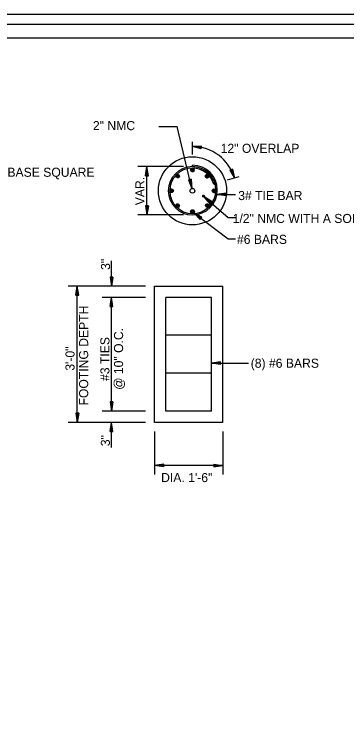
# Model space of a CAD drawing. Extents: x 1695551 to 1695718, y 544410 to 544516.
# Drawn here: x 1695642.8 to 1695670.2, y 544457.3 to 544516.2 of the extents above; entities that cross this region are included whole.
import ezdxf

# ---------------------------------------------------------------- set-up
doc = ezdxf.new("R2010")
doc.units = 0
for name, color, linetype in [('0_Plot Shape', 7, 'Continuous'), ('R_Border', 7, 'Continuous'), ('R_Draft', 7, 'Continuous'), ('R_No Plot', 7, 'Continuous')]:
    doc.layers.add(name, color=color, linetype=linetype)

msp = doc.modelspace()

# ---------------------------------------------------------------- linework, layer by layer
at = {"layer": '0_Plot Shape'}
msp.add_lwpolyline([(1695551.694, 544515.386), (1695716.694, 544515.386), (1695716.694, 544410.386), (1695551.694, 544410.386)], close=True, dxfattribs=at)
at = {"layer": 'R_Border'}
msp.add_line((1695557.469, 544514.251), (1695715.559, 544514.251), dxfattribs=at)
at = {"layer": 'R_Draft'}
for p, q in [((1695654.739, 544506.923), (1695656.274, 544506.923)), ((1695657.478, 544501.819), (1695656.274, 544506.923)), ((1695657.523, 544504.629), (1695657.523, 544505.656)), ((1695658.282, 544505.313), (1695657.524, 544505.297)), ((1695658.253, 544505.09), (1695657.524, 544505.297)), ((1695658.279, 544505.295), (1695657.648, 544505.281)), ((1695658.256, 544505.109), (1695657.648, 544505.281)), ((1695658.277, 544505.276), (1695657.776, 544505.264)), ((1695658.258, 544505.128), (1695657.776, 544505.264)), ((1695658.275, 544505.257), (1695657.9, 544505.249)), ((1695658.26, 544505.146), (1695657.9, 544505.249)), ((1695658.272, 544505.238), (1695658.026, 544505.233)), ((1695658.263, 544505.166), (1695658.026, 544505.233)), ((1695658.27, 544505.219), (1695658.15, 544505.217)), ((1695658.265, 544505.184), (1695658.15, 544505.217)), ((1695658.253, 544505.09), (1695658.282, 544505.313)), ((1695657.523, 544503.622), (1695657.523, 544503.739)), ((1695656.773, 544503.622), (1695653.023, 544503.622)), ((1695653.66, 544502.872), (1695653.773, 544503.622)), ((1695653.679, 544502.872), (1695653.773, 544503.497)), ((1695653.698, 544502.872), (1695653.773, 544503.368)), ((1695653.717, 544502.872), (1695653.773, 544503.243)), ((1695653.736, 544502.872), (1695653.773, 544503.116)), ((1695653.773, 544499.637), (1695653.773, 544503.622)), ((1695653.885, 544502.872), (1695653.773, 544503.622)), ((1695653.866, 544502.872), (1695653.773, 544503.497)), ((1695653.847, 544502.872), (1695653.773, 544503.368)), ((1695653.828, 544502.872), (1695653.773, 544503.243)), ((1695653.809, 544502.872), (1695653.773, 544503.116)), ((1695657.373, 544503.348), (1695657.529, 544503.504)), ((1695657.374, 544503.375), (1695657.501, 544503.503)), ((1695657.376, 544503.324), (1695657.553, 544503.501)), ((1695657.381, 544503.303), (1695657.574, 544503.495)), ((1695657.384, 544503.412), (1695657.465, 544503.493)), ((1695657.39, 544503.285), (1695657.592, 544503.487)), ((1695657.4, 544503.268), (1695657.608, 544503.477)), ((1695657.411, 544503.254), (1695657.623, 544503.465)), ((1695657.425, 544503.241), (1695657.636, 544503.452)), ((1695657.44, 544503.229), (1695657.648, 544503.437)), ((1695657.457, 544503.219), (1695657.657, 544503.42)), ((1695657.476, 544503.212), (1695657.665, 544503.401)), ((1695657.497, 544503.206), (1695657.67, 544503.38)), ((1695657.521, 544503.204), (1695657.673, 544503.356)), ((1695657.55, 544503.207), (1695657.67, 544503.327)), ((1695657.59, 544503.22), (1695657.656, 544503.286)), ((1695660.815, 544503.413), (1695660.605, 544503.332)), ((1695660.605, 544503.332), (1695660.978, 544502.672)), ((1695660.622, 544503.339), (1695660.933, 544502.789)), ((1695660.64, 544503.346), (1695660.887, 544502.909)), ((1695660.658, 544503.352), (1695660.842, 544503.026)), ((1695660.675, 544503.359), (1695660.797, 544503.145)), ((1695660.693, 544503.366), (1695660.752, 544503.262)), ((1695660.726, 544503.379), (1695660.752, 544503.262)), ((1695660.744, 544503.385), (1695660.797, 544503.145)), ((1695660.762, 544503.392), (1695660.842, 544503.026)), ((1695660.779, 544503.399), (1695660.887, 544502.909)), ((1695660.797, 544503.406), (1695660.933, 544502.789)), ((1695660.815, 544503.413), (1695660.978, 544502.672)), ((1695653.66, 544502.872), (1695653.885, 544502.872)), ((1695653.755, 544502.872), (1695653.773, 544502.99)), ((1695653.79, 544502.872), (1695653.773, 544502.99)), ((1695656.153, 544502.856), (1695656.296, 544502.999)), ((1695656.154, 544502.83), (1695656.322, 544502.998)), ((1695656.158, 544502.887), (1695656.265, 544502.994)), ((1695656.158, 544502.808), (1695656.344, 544502.993)), ((1695656.165, 544502.789), (1695656.363, 544502.986)), ((1695656.175, 544502.771), (1695656.381, 544502.977)), ((1695656.181, 544502.937), (1695656.215, 544502.971)), ((1695656.185, 544502.756), (1695656.396, 544502.966)), ((1695656.198, 544502.742), (1695656.41, 544502.954)), ((1695656.212, 544502.729), (1695656.422, 544502.939)), ((1695656.228, 544502.719), (1695656.433, 544502.923)), ((1695656.246, 544502.71), (1695656.442, 544502.906)), ((1695656.266, 544502.704), (1695656.448, 544502.886)), ((1695656.289, 544502.7), (1695656.452, 544502.863)), ((1695656.315, 544502.7), (1695656.452, 544502.837)), ((1695656.348, 544502.706), (1695656.446, 544502.804)), ((1695657.42, 544502.576), (1695657.201, 544502.525)), ((1695657.201, 544502.525), (1695657.478, 544501.819)), ((1695657.219, 544502.53), (1695657.45, 544501.941)), ((1695657.238, 544502.534), (1695657.421, 544502.067)), ((1695657.256, 544502.538), (1695657.393, 544502.189)), ((1695657.274, 544502.542), (1695657.365, 544502.313)), ((1695657.293, 544502.547), (1695657.337, 544502.435)), ((1695657.327, 544502.554), (1695657.337, 544502.435)), ((1695657.346, 544502.559), (1695657.365, 544502.313)), ((1695657.365, 544502.563), (1695657.393, 544502.189)), ((1695657.383, 544502.567), (1695657.421, 544502.067)), ((1695657.402, 544502.571), (1695657.45, 544501.941)), ((1695657.42, 544502.576), (1695657.478, 544501.819)), ((1695658.576, 544502.845), (1695658.713, 544502.982)), ((1695658.576, 544502.818), (1695658.739, 544502.981)), ((1695658.58, 544502.796), (1695658.762, 544502.978)), ((1695658.583, 544502.878), (1695658.679, 544502.975)), ((1695658.586, 544502.776), (1695658.782, 544502.971)), ((1695658.595, 544502.758), (1695658.8, 544502.962)), ((1695658.606, 544502.742), (1695658.816, 544502.952)), ((1695658.618, 544502.728), (1695658.83, 544502.94)), ((1695658.632, 544502.715), (1695658.842, 544502.926)), ((1695658.647, 544502.704), (1695658.853, 544502.91)), ((1695658.665, 544502.695), (1695658.863, 544502.893)), ((1695658.684, 544502.688), (1695658.87, 544502.873)), ((1695658.706, 544502.683), (1695658.874, 544502.851)), ((1695658.731, 544502.682), (1695658.875, 544502.826)), ((1695658.763, 544502.687), (1695658.871, 544502.795)), ((1695658.812, 544502.709), (1695658.848, 544502.746)), ((1695661.337, 544502.78), (1695660.395, 544502.496)), ((1695659.389, 544502.193), (1695659.277, 544502.159)), ((1695655.648, 544501.637), (1695655.79, 544501.779)), ((1695655.649, 544501.611), (1695655.816, 544501.778)), ((1695655.653, 544501.589), (1695655.838, 544501.774)), ((1695655.653, 544501.668), (1695655.759, 544501.774)), ((1695655.66, 544501.569), (1695655.857, 544501.767)), ((1695655.669, 544501.552), (1695655.875, 544501.758)), ((1695655.678, 544501.72), (1695655.707, 544501.749)), ((1695655.68, 544501.536), (1695655.891, 544501.747)), ((1695655.692, 544501.522), (1695655.905, 544501.734)), ((1695655.707, 544501.51), (1695655.917, 544501.72)), ((1695655.723, 544501.499), (1695655.927, 544501.704)), ((1695655.74, 544501.491), (1695655.936, 544501.686)), ((1695655.76, 544501.484), (1695655.943, 544501.667)), ((1695655.783, 544501.48), (1695655.947, 544501.644)), ((1695655.809, 544501.48), (1695655.947, 544501.618)), ((1695655.842, 544501.486), (1695655.941, 544501.585)), ((1695659.149, 544501.631), (1695659.297, 544501.779)), ((1695659.151, 544501.606), (1695659.322, 544501.778)), ((1695659.153, 544501.661), (1695659.267, 544501.776)), ((1695659.156, 544501.585), (1695659.344, 544501.773)), ((1695659.163, 544501.566), (1695659.363, 544501.765)), ((1695659.169, 544501.704), (1695659.224, 544501.759)), ((1695659.173, 544501.549), (1695659.38, 544501.756)), ((1695659.184, 544501.533), (1695659.395, 544501.745)), ((1695659.197, 544501.52), (1695659.409, 544501.732)), ((1695659.211, 544501.508), (1695659.421, 544501.717)), ((1695659.228, 544501.497), (1695659.431, 544501.701)), ((1695659.246, 544501.489), (1695659.439, 544501.683)), ((1695659.266, 544501.483), (1695659.445, 544501.662)), ((1695659.289, 544501.48), (1695659.449, 544501.639)), ((1695659.316, 544501.48), (1695659.448, 544501.612)), ((1695659.351, 544501.489), (1695659.44, 544501.577)), ((1695660.291, 544501.433), (1695659.541, 544501.321)), ((1695660.291, 544501.415), (1695659.666, 544501.321)), ((1695660.291, 544501.396), (1695659.795, 544501.321)), ((1695660.291, 544501.377), (1695659.92, 544501.321)), ((1695660.291, 544501.358), (1695660.047, 544501.321)), ((1695660.291, 544501.208), (1695660.291, 544501.433)), ((1695658.369, 544501.192), (1695658.446, 544501.27)), ((1695658.372, 544501.169), (1695658.469, 544501.267)), ((1695658.377, 544501.228), (1695658.411, 544501.261)), ((1695658.38, 544501.151), (1695658.488, 544501.258)), ((1695658.392, 544501.136), (1695658.502, 544501.247)), ((1695658.407, 544501.125), (1695658.514, 544501.232)), ((1695658.425, 544501.117), (1695658.522, 544501.213)), ((1695658.449, 544501.114), (1695658.525, 544501.19)), ((1695658.486, 544501.124), (1695658.514, 544501.153)), ((1695658.502, 544501.135), (1695660.474, 544499.414)), ((1695658.996, 544500.56), (1695658.502, 544501.135)), ((1695659.143, 544500.73), (1695658.502, 544501.135)), ((1695659.008, 544500.574), (1695658.597, 544501.053)), ((1695659.131, 544500.716), (1695658.597, 544501.053)), ((1695659.118, 544500.701), (1695658.694, 544500.969)), ((1695659.021, 544500.588), (1695658.694, 544500.969)), ((1695659.033, 544500.603), (1695658.789, 544500.887)), ((1695659.106, 544500.687), (1695658.789, 544500.887)), ((1695659.094, 544500.673), (1695658.885, 544500.804)), ((1695659.046, 544500.617), (1695658.885, 544500.804)), ((1695659.541, 544501.321), (1695661.075, 544501.321)), ((1695660.291, 544501.208), (1695659.541, 544501.321)), ((1695660.291, 544501.227), (1695659.666, 544501.321)), ((1695660.291, 544501.246), (1695659.795, 544501.321)), ((1695660.291, 544501.265), (1695659.92, 544501.321)), ((1695660.291, 544501.285), (1695660.047, 544501.321)), ((1695660.291, 544501.339), (1695660.172, 544501.321)), ((1695660.291, 544501.303), (1695660.172, 544501.321)), ((1695653.66, 544500.387), (1695653.773, 544499.637)), ((1695653.885, 544500.387), (1695653.66, 544500.387)), ((1695653.679, 544500.387), (1695653.773, 544499.762)), ((1695653.698, 544500.387), (1695653.773, 544499.891)), ((1695653.717, 544500.387), (1695653.773, 544500.016)), ((1695653.736, 544500.387), (1695653.773, 544500.143)), ((1695653.755, 544500.387), (1695653.773, 544500.268)), ((1695653.885, 544500.387), (1695653.773, 544499.637)), ((1695653.809, 544500.387), (1695653.773, 544500.143)), ((1695653.847, 544500.387), (1695653.773, 544499.891)), ((1695653.866, 544500.387), (1695653.773, 544499.762)), ((1695653.828, 544500.387), (1695653.773, 544500.016)), ((1695653.79, 544500.387), (1695653.773, 544500.268)), ((1695656.153, 544500.396), (1695656.317, 544500.559)), ((1695656.153, 544500.422), (1695656.29, 544500.559)), ((1695656.157, 544500.373), (1695656.339, 544500.555)), ((1695656.16, 544500.455), (1695656.257, 544500.552)), ((1695656.164, 544500.353), (1695656.359, 544500.548)), ((1695656.172, 544500.335), (1695656.377, 544500.54)), ((1695656.183, 544500.319), (1695656.393, 544500.529)), ((1695656.195, 544500.305), (1695656.407, 544500.517)), ((1695656.209, 544500.292), (1695656.42, 544500.503)), ((1695656.225, 544500.281), (1695656.431, 544500.488)), ((1695656.242, 544500.272), (1695656.44, 544500.47)), ((1695656.262, 544500.265), (1695656.447, 544500.451)), ((1695656.284, 544500.261), (1695656.452, 544500.429)), ((1695656.309, 544500.26), (1695656.453, 544500.403)), ((1695656.34, 544500.264), (1695656.448, 544500.372)), ((1695656.39, 544500.287), (1695656.425, 544500.322)), ((1695658.6, 544500.409), (1695658.742, 544500.552)), ((1695658.601, 544500.384), (1695658.768, 544500.551)), ((1695658.605, 544500.362), (1695658.79, 544500.547)), ((1695658.605, 544500.441), (1695658.711, 544500.547)), ((1695658.612, 544500.342), (1695658.81, 544500.54)), ((1695658.621, 544500.325), (1695658.827, 544500.531)), ((1695658.63, 544500.492), (1695658.659, 544500.522)), ((1695658.632, 544500.309), (1695658.843, 544500.52)), ((1695658.645, 544500.295), (1695658.857, 544500.507)), ((1695658.659, 544500.283), (1695658.869, 544500.493)), ((1695658.675, 544500.272), (1695658.88, 544500.477)), ((1695658.693, 544500.263), (1695658.888, 544500.459)), ((1695658.713, 544500.257), (1695658.895, 544500.439)), ((1695658.735, 544500.253), (1695658.899, 544500.417)), ((1695658.761, 544500.253), (1695658.899, 544500.39)), ((1695658.794, 544500.259), (1695658.893, 544500.358)), ((1695659.081, 544500.658), (1695658.98, 544500.722)), ((1695659.058, 544500.631), (1695658.98, 544500.722)), ((1695658.996, 544500.56), (1695659.143, 544500.73)), ((1695656.773, 544499.637), (1695653.023, 544499.637)), ((1695657.367, 544499.896), (1695657.537, 544500.066)), ((1695657.367, 544499.922), (1695657.511, 544500.066)), ((1695657.371, 544499.873), (1695657.56, 544500.062)), ((1695657.373, 544499.955), (1695657.478, 544500.06)), ((1695657.377, 544499.853), (1695657.58, 544500.056)), ((1695657.386, 544499.835), (1695657.598, 544500.047)), ((1695657.396, 544499.819), (1695657.614, 544500.037)), ((1695657.407, 544500.016), (1695657.417, 544500.026)), ((1695657.408, 544499.804), (1695657.629, 544500.025)), ((1695657.421, 544499.791), (1695657.642, 544500.012)), ((1695657.437, 544499.78), (1695657.653, 544499.997)), ((1695657.453, 544499.77), (1695657.663, 544499.98)), ((1695657.472, 544499.763), (1695657.67, 544499.961)), ((1695657.493, 544499.757), (1695657.676, 544499.94)), ((1695657.517, 544499.754), (1695657.679, 544499.916)), ((1695657.545, 544499.756), (1695657.677, 544499.888)), ((1695657.581, 544499.766), (1695657.667, 544499.852)), ((1695657.635, 544499.801), (1695660.474, 544497.654)), ((1695658.166, 544499.26), (1695657.635, 544499.801)), ((1695658.301, 544499.44), (1695657.635, 544499.801)), ((1695658.177, 544499.275), (1695657.735, 544499.726)), ((1695658.29, 544499.425), (1695657.735, 544499.726)), ((1695658.279, 544499.41), (1695657.838, 544499.648)), ((1695658.189, 544499.29), (1695657.838, 544499.648)), ((1695658.2, 544499.305), (1695657.937, 544499.573)), ((1695658.267, 544499.395), (1695657.937, 544499.573)), ((1695658.256, 544499.379), (1695658.039, 544499.497)), ((1695658.212, 544499.321), (1695658.039, 544499.497)), ((1695658.244, 544499.364), (1695658.139, 544499.421)), ((1695658.223, 544499.336), (1695658.139, 544499.421)), ((1695658.166, 544499.26), (1695658.301, 544499.44)), ((1695660.474, 544499.414), (1695661.075, 544499.414)), ((1695660.474, 544497.654), (1695661.075, 544497.654)), ((1695650.839, 544493.762), (1695650.839, 544495.847)), ((1695650.726, 544494.512), (1695650.839, 544493.762)), ((1695650.951, 544494.512), (1695650.726, 544494.512)), ((1695650.745, 544494.512), (1695650.839, 544493.888)), ((1695650.764, 544494.512), (1695650.839, 544494.017)), ((1695650.783, 544494.512), (1695650.839, 544494.142)), ((1695650.802, 544494.512), (1695650.839, 544494.269)), ((1695650.821, 544494.512), (1695650.839, 544494.394)), ((1695650.951, 544494.512), (1695650.839, 544493.762)), ((1695650.875, 544494.512), (1695650.839, 544494.269)), ((1695650.914, 544494.512), (1695650.839, 544494.017)), ((1695650.933, 544494.512), (1695650.839, 544493.888)), ((1695650.895, 544494.512), (1695650.839, 544494.142)), ((1695650.857, 544494.512), (1695650.839, 544494.394)), ((1695653.651, 544493.762), (1695647.276, 544493.762)), ((1695647.914, 544493.012), (1695648.026, 544493.762)), ((1695648.026, 544482.512), (1695648.026, 544493.762)), ((1695648.139, 544493.012), (1695648.026, 544493.762)), ((1695654.401, 544482.512), (1695654.401, 544493.762)), ((1695654.401, 544493.762), (1695660.026, 544493.762)), ((1695660.026, 544482.512), (1695660.026, 544493.762)), ((1695647.933, 544493.012), (1695648.026, 544493.637)), ((1695647.952, 544493.012), (1695648.026, 544493.508)), ((1695647.971, 544493.012), (1695648.026, 544493.383)), ((1695647.99, 544493.012), (1695648.026, 544493.256)), ((1695648.009, 544493.012), (1695648.026, 544493.131)), ((1695648.12, 544493.012), (1695648.026, 544493.637)), ((1695648.101, 544493.012), (1695648.026, 544493.508)), ((1695648.082, 544493.012), (1695648.026, 544493.383)), ((1695648.063, 544493.012), (1695648.026, 544493.256)), ((1695648.044, 544493.012), (1695648.026, 544493.131)), ((1695647.914, 544493.012), (1695648.139, 544493.012)), ((1695653.651, 544492.825), (1695650.089, 544492.825)), ((1695650.726, 544492.075), (1695650.839, 544492.825)), ((1695650.745, 544492.075), (1695650.839, 544492.7)), ((1695650.764, 544492.075), (1695650.839, 544492.571)), ((1695650.839, 544483.45), (1695650.839, 544492.825)), ((1695650.951, 544492.075), (1695650.839, 544492.825)), ((1695650.933, 544492.075), (1695650.839, 544492.7)), ((1695650.914, 544492.075), (1695650.839, 544492.571)), ((1695659.089, 544492.825), (1695655.339, 544492.825)), ((1695655.339, 544483.45), (1695655.339, 544492.825)), ((1695659.089, 544483.45), (1695659.089, 544492.825)), ((1695650.726, 544492.075), (1695650.951, 544492.075)), ((1695650.783, 544492.075), (1695650.839, 544492.446)), ((1695650.803, 544492.075), (1695650.839, 544492.319)), ((1695650.821, 544492.075), (1695650.839, 544492.193)), ((1695650.895, 544492.075), (1695650.839, 544492.446)), ((1695650.876, 544492.075), (1695650.839, 544492.319)), ((1695650.857, 544492.075), (1695650.839, 544492.193)), ((1695659.089, 544489.7), (1695655.339, 544489.7)), ((1695659.841, 544487.51), (1695659.091, 544487.397)), ((1695659.841, 544487.285), (1695659.091, 544487.397)), ((1695659.091, 544487.397), (1695662.145, 544487.397)), ((1695659.841, 544487.491), (1695659.216, 544487.397)), ((1695659.841, 544487.303), (1695659.216, 544487.397)), ((1695659.841, 544487.472), (1695659.345, 544487.397)), ((1695659.841, 544487.323), (1695659.345, 544487.397)), ((1695659.841, 544487.453), (1695659.47, 544487.397)), ((1695659.841, 544487.341), (1695659.47, 544487.397)), ((1695659.841, 544487.434), (1695659.597, 544487.397)), ((1695659.841, 544487.361), (1695659.597, 544487.397)), ((1695659.841, 544487.415), (1695659.722, 544487.397)), ((1695659.841, 544487.38), (1695659.722, 544487.397)), ((1695659.841, 544487.285), (1695659.841, 544487.51)), ((1695659.089, 544486.575), (1695655.339, 544486.575)), ((1695650.726, 544484.2), (1695650.839, 544483.45)), ((1695650.951, 544484.2), (1695650.726, 544484.2)), ((1695650.745, 544484.2), (1695650.839, 544483.575)), ((1695650.764, 544484.2), (1695650.839, 544483.704)), ((1695650.783, 544484.2), (1695650.839, 544483.829)), ((1695650.802, 544484.2), (1695650.839, 544483.956)), ((1695650.821, 544484.2), (1695650.839, 544484.081)), ((1695650.951, 544484.2), (1695650.839, 544483.45)), ((1695650.875, 544484.2), (1695650.839, 544483.956)), ((1695650.914, 544484.2), (1695650.839, 544483.704)), ((1695650.933, 544484.2), (1695650.839, 544483.575)), ((1695650.895, 544484.2), (1695650.839, 544483.829)), ((1695650.857, 544484.2), (1695650.839, 544484.081)), ((1695647.914, 544483.262), (1695648.026, 544482.512)), ((1695648.139, 544483.262), (1695647.914, 544483.262)), ((1695647.933, 544483.262), (1695648.026, 544482.638)), ((1695647.952, 544483.262), (1695648.026, 544482.767)), ((1695647.971, 544483.262), (1695648.026, 544482.892)), ((1695647.99, 544483.262), (1695648.026, 544483.019)), ((1695648.009, 544483.262), (1695648.026, 544483.144)), ((1695648.139, 544483.262), (1695648.026, 544482.512)), ((1695648.063, 544483.262), (1695648.026, 544483.019)), ((1695648.101, 544483.262), (1695648.026, 544482.767)), ((1695648.12, 544483.262), (1695648.026, 544482.638)), ((1695648.082, 544483.262), (1695648.026, 544482.892)), ((1695648.044, 544483.262), (1695648.026, 544483.144)), ((1695653.651, 544483.45), (1695650.089, 544483.45)), ((1695659.089, 544483.45), (1695655.339, 544483.45)), ((1695653.651, 544482.512), (1695647.276, 544482.512)), ((1695650.726, 544481.762), (1695650.839, 544482.512)), ((1695650.839, 544480.428), (1695650.839, 544482.512)), ((1695650.951, 544481.762), (1695650.839, 544482.512)), ((1695660.026, 544482.512), (1695654.401, 544482.512)), ((1695650.745, 544481.762), (1695650.839, 544482.387)), ((1695650.764, 544481.762), (1695650.839, 544482.258)), ((1695650.783, 544481.762), (1695650.839, 544482.133)), ((1695650.803, 544481.762), (1695650.839, 544482.006)), ((1695650.933, 544481.762), (1695650.839, 544482.387)), ((1695650.914, 544481.762), (1695650.839, 544482.258)), ((1695650.895, 544481.762), (1695650.839, 544482.133)), ((1695650.876, 544481.762), (1695650.839, 544482.006)), ((1695650.726, 544481.762), (1695650.951, 544481.762)), ((1695650.821, 544481.762), (1695650.839, 544481.881)), ((1695650.857, 544481.762), (1695650.839, 544481.881)), ((1695654.401, 544481.762), (1695654.401, 544478.2)), ((1695660.026, 544481.762), (1695660.026, 544478.2)), ((1695655.151, 544479.062), (1695654.401, 544478.95)), ((1695655.151, 544479.044), (1695654.527, 544478.95)), ((1695655.151, 544479.025), (1695654.656, 544478.95)), ((1695655.151, 544479.006), (1695654.781, 544478.95)), ((1695655.151, 544478.987), (1695654.908, 544478.95)), ((1695655.151, 544478.837), (1695655.151, 544479.062)), ((1695659.276, 544479.062), (1695660.026, 544478.95)), ((1695659.276, 544479.062), (1695659.276, 544478.837)), ((1695659.276, 544479.044), (1695659.901, 544478.95)), ((1695659.276, 544479.025), (1695659.772, 544478.95)), ((1695659.276, 544479.006), (1695659.647, 544478.95)), ((1695659.276, 544478.986), (1695659.52, 544478.95)), ((1695660.026, 544478.95), (1695654.401, 544478.95)), ((1695655.151, 544478.837), (1695654.401, 544478.95)), ((1695655.151, 544478.856), (1695654.527, 544478.95)), ((1695655.151, 544478.875), (1695654.656, 544478.95)), ((1695655.151, 544478.894), (1695654.781, 544478.95)), ((1695655.151, 544478.914), (1695654.908, 544478.95)), ((1695655.151, 544478.968), (1695655.033, 544478.95)), ((1695655.151, 544478.932), (1695655.033, 544478.95)), ((1695659.276, 544478.968), (1695659.395, 544478.95)), ((1695659.276, 544478.837), (1695660.026, 544478.95)), ((1695659.276, 544478.913), (1695659.52, 544478.95)), ((1695659.276, 544478.875), (1695659.772, 544478.95)), ((1695659.276, 544478.856), (1695659.901, 544478.95)), ((1695659.276, 544478.894), (1695659.647, 544478.95)), ((1695659.276, 544478.932), (1695659.395, 544478.95))]:
    msp.add_line(p, q, dxfattribs=at)
for centre, radius in [((1695657.523, 544501.629), 2.812), ((1695657.523, 544503.354), 0.15), ((1695656.303, 544502.849), 0.15), ((1695658.725, 544502.832), 0.15), ((1695655.798, 544501.629), 0.15), ((1695657.523, 544501.629), 0.195), ((1695659.299, 544501.629), 0.15), ((1695658.447, 544501.192), 0.0781), ((1695656.303, 544500.41), 0.15), ((1695658.75, 544500.402), 0.15), ((1695657.523, 544499.911), 0.156)]:
    msp.add_circle(centre, radius, dxfattribs=at)
for centre, radius, start, end in [((1695657.523, 544501.688), 3.593, 15.89385, 90), ((1695657.523, 544501.688), 2.051, 270, 90), ((1695657.523, 544501.629), 1.992, 90, 270), ((1695657.523, 544501.629), 1.875, 90, 270), ((1695657.523, 544501.688), 1.934, 270, 90), ((1695657.523, 544501.688), 1.816, 43.68938, 90), ((1695657.523, 544501.688), 1.816, 15.01624, 90)]:
    msp.add_arc(centre, radius, start, end, dxfattribs=at)
at = {"layer": 'R_No Plot'}
msp.add_line((1695551.268, 544516.198), (1695717.935, 544516.198), dxfattribs=at)
msp.add_lwpolyline([(1695551.265, 544516.198), (1695717.935, 544516.198), (1695717.935, 544409.529), (1695551.265, 544409.529)], close=True, dxfattribs=at)

# ---------------------------------------------------------------- texts
at = {"layer": 'R_Draft'}
for s, p in [('2" NMC', (1695649.315, 544506.634)), ('12" OVERLAP', (1695659.852, 544504.759)), ('ANCHOR BASE SQUARE', (1695637.634, 544502.785)), ('3# TIE BAR', (1695661.299, 544500.862)), (' 1/2" NMC WITH A SOLID 1C/#8 A.W.G., E.G.C.', (1695660.562, 544498.97)), ('#6 BARS', (1695661.194, 544497.244)), ('(8) #6 BARS', (1695662.328, 544487.023)), ('DIA. 1\'-6"', (1695654.939, 544477.584))]:
    msp.add_text(s, height=0.75, dxfattribs=at).set_placement(p)
for s, p in [('VAR.', (1695653.56, 544500.437)), ('3"', (1695650.728, 544495.101)), ('FOOTING DEPTH', (1695648.923, 544483.909)), ('@ 10" O.C.', (1695651.802, 544485.201)), ('#3 TIES', (1695650.677, 544485.934)), ('3\'-0"', (1695647.798, 544486.782)), ('3"', (1695650.717, 544480.548))]:
    msp.add_text(s, height=0.75, rotation=90, dxfattribs=at).set_placement(p)

doc.saveas('drawing.dxf')
